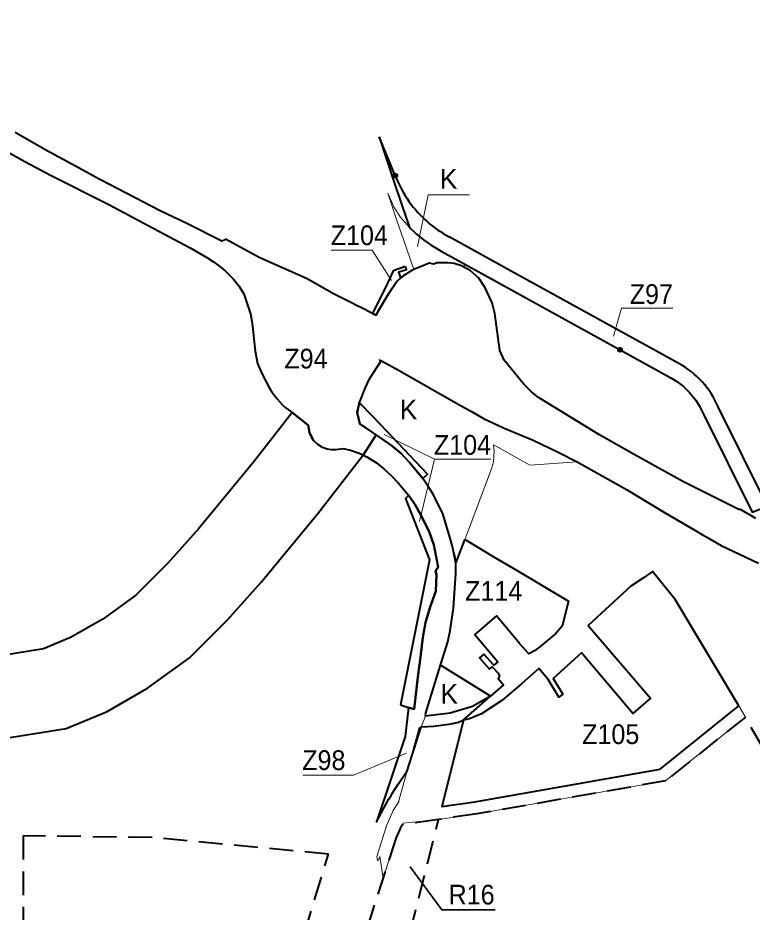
# Model space of a CAD drawing. Extents: x -650276 to -642489, y -1074311 to -1066658.
# Drawn here: x -647038 to -646145, y -1069297 to -1068210 of the extents above; entities that cross this region are included whole.
import ezdxf

# ---------------------------------------------------------------- set-up
doc = ezdxf.new("R2010")
doc.units = 0
doc.header["$LTSCALE"] = 9.6
doc.header["$PDMODE"] = 32
doc.header["$PDSIZE"] = 4.8
doc.linetypes.add('MEDIUM_DASHED', pattern=[4.5, 3, -1.5])
for name, color, linetype, lineweight in [('44', 7, 'Continuous', 40), ('45', 7, 'Continuous', 40), ('46', 7, 'Continuous', 13), ('47', 7, 'Continuous', 13), ('48', 7, 'Continuous', 35), ('61', 7, 'MEDIUM_DASHED', 40), ('62', 7, 'Continuous', 35)]:
    doc.layers.add(name, color=color, linetype=linetype, lineweight=lineweight)

msp = doc.modelspace()

# ---------------------------------------------------------------- linework, layer by layer
at = {"layer": '44'}
msp.add_line((-646578.881, -1068401.54), (-646598.635, -1068354.436), dxfattribs=at)
for points in [[(-647419.713, -1068138.871), (-647405.71, -1068151.74), (-647372.38, -1068179.01), (-647337.74, -1068205.67), (-647334.62, -1068208.02), (-647307.39, -1068227.44), (-647281.64, -1068244.34), (-647234.11, -1068273.04), (-647230.83, -1068274.93), (-647174.56, -1068306.35), (-647142.788, -1068322.462), (-647130.29, -1068328.8), (-647079.16, -1068357.01), (-647032.91, -1068382.51), (-647029.23, -1068384.46), (-646997.06, -1068401.37), (-646929.56, -1068435.42), (-646927.06, -1068436.66)], [(-646545.57, -1068511.42), (-646556.22, -1068515.84), (-646559.72, -1068517.29), (-646569.61, -1068524.1), (-646572.02, -1068526.07), (-646577.07, -1068530.2), (-646587.28, -1068545.28), (-646599.75, -1068566.49), (-646602.21, -1068571.5), (-646606.59, -1068569.33), (-646620.94, -1068561.96), (-646625.86, -1068559.47), (-646631.18, -1068556.77), (-646653.21, -1068545.58), (-646686.84, -1068526.89), (-646686.84, -1068526.89), (-646743.69, -1068501.76), (-646785.05, -1068479.12), (-646787.55, -1068480.36), (-646789.49, -1068481.31), (-646832.29, -1068460.04), (-646864.48, -1068444.64), (-646936.47, -1068407.23), (-646938.95, -1068405.8), (-646967.64, -1068390), (-647002.71, -1068371.09), (-647040.77, -1068349.4)], [(-646598.635, -1068354.436), (-646579.62, -1068411.29), (-646564.78, -1068455.41), (-646561.544, -1068464.842)], [(-646927.06, -1068436.66), (-646854.18, -1068475.8), (-646828.2, -1068489.61), (-646807.82, -1068501.17), (-646799.79, -1068506.39), (-646790.66, -1068513.24), (-646785.34, -1068517.77), (-646779.93, -1068522.9), (-646775.44, -1068527.74), (-646768.95, -1068535.8), (-646763.1, -1068545.18), (-646754.92, -1068569.81), (-646753.35, -1068578.6), (-646752.59, -1068584.55), (-646749.35, -1068615.18), (-646746.32, -1068630.23), (-646740.91, -1068642.34), (-646735.62, -1068652.21), (-646732.25, -1068659.06), (-646729.34, -1068663.94), (-646722.6, -1068673.11), (-646716.39, -1068679.8), (-646716.39, -1068679.8), (-646712.93, -1068683), (-646704.316, -1068689.698), (-646684.7, -1068704.95), (-646682.98, -1068714.07), (-646680.88, -1068719.28), (-646678.08, -1068723.7)], [(-646561.544, -1068464.842), (-646553.677, -1068472.283), (-646544.525, -1068479.79), (-646535.245, -1068486.342), (-646523.105, -1068493.54), (-646493.511, -1068509.855), (-646305.678, -1068613.404)], [(-646234.342, -1068629.893), (-646234.342, -1068629.892), (-646438.626, -1068517.274), (-646513.45, -1068476.025), (-646513.567, -1068475.963)], [(-646337.93, -1068712.4), (-646404.83, -1068671.52), (-646413.45, -1068664.71), (-646422.32, -1068655.58), (-646425.11, -1068652.37), (-646446.54, -1068626.14), (-646451.82, -1068614.31), (-646458.03, -1068569.26), (-646461.14, -1068556.34), (-646469.51, -1068538.15), (-646477.41, -1068526.45), (-646487.92, -1068516.87), (-646498.48, -1068511.26), (-646507.4, -1068508.45), (-646514.39, -1068507.56), (-646528.18, -1068507.58), (-646531.9, -1068509.25), (-646537.71, -1068508.16), (-646545.57, -1068511.42)], [(-646305.678, -1068613.404), (-646243.997, -1068647.407), (-646236.707, -1068651.891), (-646228.691, -1068658.051), (-646221.348, -1068665.144), (-646213.659, -1068674.696), (-646209.179, -1068681.795), (-646204.654, -1068690.937), (-646145.083, -1068810.83), (-646126.317, -1068803.654), (-646186.371, -1068682.825)], [(-646602.095, -1068716.98), (-646622.01, -1068703.3), (-646625.35, -1068689.7), (-646622.68, -1068678.75), (-646615.19, -1068659.11), (-646609.7, -1068647.84), (-646597.4, -1068628.74), (-646596.28, -1068626.52), (-646596.28, -1068626.52), (-646573.14, -1068638.98), (-646545.73, -1068654.81), (-646545.73, -1068654.81), (-646501.64, -1068679.81), (-646486.23, -1068688.54), (-646470.65, -1068697.38), (-646448.02, -1068707.99), (-646444.51, -1068709.64), (-646411.3, -1068723.11), (-646380.94, -1068737.81), (-646357.87, -1068749.64), (-646297.08, -1068783.8), (-646288.37, -1068789.04), (-646251.73, -1068811.04), (-646214.92, -1068832.85), (-646208.7, -1068836.39), (-646205.48, -1068838.23), (-646199.24, -1068841.79), (-646195.52, -1068843.92), (-646182.57, -1068851.3), (-646137.23, -1068872.6)], [(-646704.316, -1068689.698), (-646725.374, -1068716.786), (-646751.116, -1068749.975), (-646817.718, -1068830.545), (-646855.506, -1068872.883), (-646894.206, -1068911.595), (-646934.465, -1068940.759)], [(-646617.991, -1068741.504), (-646622.62, -1068739.32), (-646634.37, -1068735.27), (-646642.04, -1068733.74), (-646651.21, -1068734.99), (-646656.47, -1068735.13), (-646661.5, -1068734.35), (-646667.17, -1068732.38), (-646673.16, -1068728.69), (-646678.08, -1068723.7), (-646680.88, -1068719.28), (-646682.98, -1068714.07), (-646684.7, -1068704.95), (-646704.316, -1068689.698)], [(-646618.655, -1068742.359), (-646617.991, -1068741.504), (-646617.991, -1068741.503), (-646602.095, -1068716.98)], [(-646539.08, -1068779.481), (-646545.32, -1068769.89), (-646561.5, -1068750.22), (-646571.91, -1068739.54), (-646583.49, -1068729.76), (-646602.095, -1068716.98), (-646617.991, -1068741.503)], [(-646140.73, -1068818.61), (-646146.85, -1068814.88), (-646150.26, -1068812.81), (-646159.1, -1068807.43), (-646161.45, -1068807.54), (-646229.44, -1068773.53), (-646288.59, -1068740.88), (-646331.26, -1068716.25), (-646337.93, -1068712.4)], [(-647065.688, -1069087.73), (-646978.92, -1069073.93), (-646929.186, -1069052.925), (-646880.163, -1069024.903), (-646829.104, -1068987.917), (-646782.784, -1068941.581), (-646741.85, -1068895.719), (-646673.05, -1068812.491), (-646618.655, -1068742.359), (-646617.991, -1068741.504)], [(-646617.991, -1068741.503), (-646613.44, -1068743.65), (-646601.86, -1068751.01), (-646592.53, -1068758.66), (-646583.98, -1068766.42), (-646575.28, -1068775.04), (-646562.49, -1068790.69), (-646554.8, -1068801.98)], [(-646509.323, -1068852.529), (-646513.27, -1068838.37), (-646521.18, -1068812.95), (-646532.92, -1068788.95), (-646539.08, -1068779.481)], [(-646554.8, -1068801.98), (-646547.68, -1068814.22), (-646547.433, -1068814.73)], [(-646547.433, -1068814.73), (-646537.35, -1068835.56), (-646532.16, -1068850.47), (-646526.64, -1068877.47), (-646530.06, -1068882.16)], [(-646524, -1068997), (-646514.91, -1068968.48), (-646514.91, -1068968.48), (-646512.07, -1068954.68), (-646507.91, -1068927.47), (-646505.12, -1068885.31), (-646505.17, -1068872.78), (-646509.323, -1068852.529)], [(-646530.06, -1068882.16), (-646528.92, -1068886.55), (-646529.44, -1068906.81), (-646533.28, -1068917.17)], [(-646533.28, -1068917.17), (-646536.54, -1068925.95), (-646542.16, -1068945.12), (-646545.42, -1068963.3), (-646549.17, -1068993.71), (-646549.81, -1068998.88), (-646550.89, -1069007.7), (-646555.84, -1069050.22), (-646559.8, -1069048.98), (-646562.61, -1069048.08)], [(-646934.465, -1068940.759), (-646973.61, -1068963.135), (-647006.63, -1068977.08), (-647076.422, -1068988.18), (-647128.674, -1068991.167), (-647199.672, -1068994.255), (-647268.348, -1068994.255), (-647338.816, -1068991.19), (-647417.895, -1068984.986), (-647502.412, -1068977.157), (-647629.424, -1068964.608), (-647699.561, -1068956.635), (-647749.978, -1068953.416)], [(-646462.98, -1069034.61), (-646485, -1069047), (-646512, -1069055), (-646542, -1069059), (-646541.71, -1069054.76), (-646524, -1068997)], [(-646547.412, -1069071.71), (-646532, -1069071), (-646511, -1069068), (-646502, -1069066), (-646496.317, -1069063.61), (-646462.98, -1069034.61)], [(-646562.61, -1069048.08), (-646566.82, -1069083.62), (-646601.82, -1069187.25), (-646586.97, -1069160.06), (-646585.42, -1069157.56), (-646583.89, -1069155.1), (-646582.46, -1069152.81), (-646582.46, -1069152.81), (-646575.4, -1069141.46), (-646564.54, -1069125.08), (-646547.412, -1069071.71)]]:
    msp.add_lwpolyline(points, dxfattribs=at)
at = {"layer": '44', "lineweight": 13}
for points in [[(-646241.379, -1068562.947), (-646303.746, -1068562.947), (-646313.477, -1068597.03)], [(-646241.379, -1068562.947), (-646303.746, -1068562.947), (-646313.477, -1068597.03)], [(-646691.216, -1069130.395), (-646629.734, -1069130.395), (-646565.156, -1069103.837)], [(-646691.216, -1069130.395), (-646629.734, -1069130.395), (-646565.156, -1069103.837)]]:
    msp.add_lwpolyline(points, dxfattribs=at)
at = {"layer": '44'}
for centre, radius, start, end in [((-646447.332, -1068351.964), 140.58, 200.6496, 215.36619), ((-646447.332, -1068351.964), 140.58, 215.36631, 241.891), ((-646287.447, -1068726.224), 110, 23.23727, 61.13296)]:
    msp.add_arc(centre, radius, start, end, dxfattribs=at)
for p in [(-646578.881, -1068401.54), (-646305.678, -1068613.404)]:
    msp.add_point(p, dxfattribs=at)
at = {"layer": '45'}
msp.add_line((-646583.49, -1068729.76), (-646571.91, -1068739.54), dxfattribs=at)
msp.add_line((-646583.49, -1068729.76), (-646571.91, -1068739.54), dxfattribs=at)
for points in [[(-646566.33, -1068512.04), (-646581.64, -1068517.24), (-646590.31, -1068536.69), (-646602.01, -1068560.15), (-646606.59, -1068569.33)], [(-646566.33, -1068512.04), (-646581.64, -1068517.24), (-646590.31, -1068536.69), (-646602.01, -1068560.15), (-646606.59, -1068569.33)], [(-646587.28, -1068545.28), (-646577.07, -1068530.2), (-646572.02, -1068526.07), (-646574.48, -1068518.75), (-646565.04, -1068515.86), (-646566.33, -1068512.04)], [(-646587.28, -1068545.28), (-646577.07, -1068530.2), (-646572.02, -1068526.07), (-646574.48, -1068518.75), (-646565.04, -1068515.86), (-646566.33, -1068512.04)], [(-646599.75, -1068566.49), (-646587.28, -1068545.28), (-646587.28, -1068545.28)], [(-646599.75, -1068566.49), (-646587.28, -1068545.28), (-646587.28, -1068545.28)], [(-646606.59, -1068569.33), (-646602.21, -1068571.5), (-646599.75, -1068566.49)], [(-646606.59, -1068569.33), (-646602.21, -1068571.5), (-646599.75, -1068566.49)], [(-646571.91, -1068739.54), (-646561.5, -1068750.22), (-646545.32, -1068769.89), (-646539.78, -1068764.65), (-646596.93, -1068704.15), (-646619.74, -1068680.15), (-646622.68, -1068678.75), (-646625.35, -1068689.7)], [(-646571.91, -1068739.54), (-646561.5, -1068750.22), (-646545.32, -1068769.89), (-646539.78, -1068764.65), (-646596.93, -1068704.15), (-646619.74, -1068680.15), (-646622.68, -1068678.75), (-646625.35, -1068689.7)], [(-646625.35, -1068689.7), (-646622.01, -1068703.3), (-646583.49, -1068729.76)], [(-646625.35, -1068689.7), (-646622.01, -1068703.3), (-646583.49, -1068729.76)], [(-646562.49, -1068790.69), (-646566.34, -1068794.32), (-646537.3, -1068868.95), (-646572.42, -1069044.94)], [(-646562.49, -1068790.69), (-646566.34, -1068794.32), (-646537.3, -1068868.95), (-646572.42, -1069044.94)], [(-646526.64, -1068877.47), (-646532.16, -1068850.47), (-646537.35, -1068835.56), (-646547.68, -1068814.22), (-646554.8, -1068801.98), (-646562.49, -1068790.69)], [(-646526.64, -1068877.47), (-646532.16, -1068850.47), (-646537.35, -1068835.56), (-646547.68, -1068814.22), (-646554.8, -1068801.98), (-646562.49, -1068790.69)], [(-646529.44, -1068906.81), (-646528.92, -1068886.55), (-646530.06, -1068882.16), (-646526.64, -1068877.47)], [(-646529.44, -1068906.81), (-646528.92, -1068886.55), (-646530.06, -1068882.16), (-646526.64, -1068877.47)], [(-646555.84, -1069050.22), (-646550.89, -1069007.7), (-646549.81, -1068998.88), (-646549.17, -1068993.71), (-646545.42, -1068963.3), (-646542.16, -1068945.12), (-646536.54, -1068925.95), (-646533.28, -1068917.17), (-646529.44, -1068906.81)], [(-646555.84, -1069050.22), (-646550.89, -1069007.7), (-646549.81, -1068998.88), (-646549.17, -1068993.71), (-646545.42, -1068963.3), (-646542.16, -1068945.12), (-646536.54, -1068925.95), (-646533.28, -1068917.17), (-646529.44, -1068906.81)], [(-646572.42, -1069044.94), (-646562.61, -1069048.08), (-646559.8, -1069048.98), (-646555.84, -1069050.22)], [(-646572.42, -1069044.94), (-646562.61, -1069048.08), (-646559.8, -1069048.98), (-646555.84, -1069050.22)]]:
    msp.add_lwpolyline(points, dxfattribs=at)
for points in [[(-646512.07, -1068954.68), (-646507.91, -1068927.47), (-646505.12, -1068885.31), (-646505.17, -1068872.78), (-646503.24, -1068867.61), (-646494.52, -1068844.29), (-646492.73, -1068845.01), (-646457.86, -1068865.8), (-646430.86, -1068881.89), (-646368.3, -1068919.19), (-646376.02, -1068949.34), (-646383.86, -1068958.24), (-646403.13, -1068974.41), (-646409.67, -1068979.3), (-646416.71, -1068983.21), (-646427.77, -1068970.39), (-646455.78, -1068936.87), (-646458.21, -1068938.99), (-646482.2, -1068959.52), (-646454.21, -1068992.73), (-646459.25, -1068996.98), (-646471.24, -1068983.41), (-646476.35, -1068987.98), (-646464.24, -1069001.49), (-646461.29, -1068998.81), (-646453.48, -1069006.75), (-646452.37, -1069010.01), (-646453.88, -1069013.1), (-646447.2, -1069020.9), (-646462.98, -1069034.61), (-646524, -1068997), (-646514.91, -1068968.48), (-646514.91, -1068968.48)], [(-646512.07, -1068954.68), (-646507.91, -1068927.47), (-646505.12, -1068885.31), (-646505.17, -1068872.78), (-646503.24, -1068867.61), (-646494.52, -1068844.29), (-646492.73, -1068845.01), (-646457.86, -1068865.8), (-646430.86, -1068881.89), (-646368.3, -1068919.19), (-646376.02, -1068949.34), (-646383.86, -1068958.24), (-646403.13, -1068974.41), (-646409.67, -1068979.3), (-646416.71, -1068983.21), (-646427.77, -1068970.39), (-646455.78, -1068936.87), (-646458.21, -1068938.99), (-646482.2, -1068959.52), (-646454.21, -1068992.73), (-646459.25, -1068996.98), (-646471.24, -1068983.41), (-646476.35, -1068987.98), (-646464.24, -1069001.49), (-646461.29, -1068998.81), (-646453.48, -1069006.75), (-646452.37, -1069010.01), (-646453.88, -1069013.1), (-646447.2, -1069020.9), (-646462.98, -1069034.61), (-646524, -1068997), (-646514.91, -1068968.48), (-646514.91, -1068968.48)], [(-646161.484, -1069046.228), (-646238.632, -1068916.799), (-646266.118, -1068883.048), (-646277.268, -1068890.446), (-646292.75, -1068900.72), (-646344.49, -1068948.736), (-646268.528, -1069036.82), (-646290.099, -1069055.423), (-646352.71, -1068981.82), (-646386.936, -1069012.936), (-646375.346, -1069032.07), (-646379.973, -1069035.889), (-646393.09, -1069014.234), (-646404.269, -1069001.033), (-646425.52, -1069019.41), (-646449.418, -1069039.804), (-646474.13, -1069055.83), (-646488.537, -1069062.169), (-646495.89, -1069063.531), (-646522.35, -1069168.648), (-646482.211, -1069162.813), (-646256.824, -1069123.414)], [(-646161.484, -1069046.228), (-646238.632, -1068916.799), (-646266.118, -1068883.048), (-646277.268, -1068890.446), (-646292.75, -1068900.72), (-646344.49, -1068948.736), (-646268.528, -1069036.82), (-646290.099, -1069055.423), (-646352.71, -1068981.82), (-646386.936, -1069012.936), (-646375.346, -1069032.07), (-646379.973, -1069035.889), (-646393.09, -1069014.234), (-646404.269, -1069001.033), (-646425.52, -1069019.41), (-646449.418, -1069039.804), (-646474.13, -1069055.83), (-646488.537, -1069062.169), (-646495.89, -1069063.531), (-646522.35, -1069168.648), (-646482.211, -1069162.813), (-646256.824, -1069123.414)]]:
    msp.add_lwpolyline(points, close=True, dxfattribs=at)
at = {"layer": '46'}
for points in [[(-646656.853, -1068492.089), (-646606.877, -1068492.089), (-646583.419, -1068529.344)], [(-646656.853, -1068492.089), (-646606.877, -1068492.089), (-646583.419, -1068529.344)], [(-646462.83, -1068746.366), (-646531.233, -1068746.366), (-646549.233, -1068822.328), (-646531.233, -1068746.366), (-646592.58, -1068716.54)], [(-646462.83, -1068746.366), (-646531.233, -1068746.366), (-646549.233, -1068822.328), (-646531.233, -1068746.366), (-646592.58, -1068716.54)]]:
    msp.add_lwpolyline(points, dxfattribs=at)
at = {"layer": '47'}
msp.add_line((-646462.98, -1069034.61), (-646524, -1068997), dxfattribs=at)
for points in [[(-646561.544, -1068464.842), (-646572.984, -1068451.81), (-646580.625, -1068439.803), (-646588.07, -1068422.96), (-646576.4, -1068457.27), (-646568.87, -1068479.14), (-646556.22, -1068515.84), (-646545.57, -1068511.42), (-646537.71, -1068508.16)], [(-646523.105, -1068493.54), (-646535.245, -1068486.342), (-646544.525, -1068479.79), (-646553.677, -1068472.283), (-646561.544, -1068464.842)], [(-646537.71, -1068508.16), (-646531.9, -1068509.25), (-646528.18, -1068507.58), (-646514.39, -1068507.56), (-646507.4, -1068508.45), (-646498.48, -1068511.26), (-646495.416, -1068512.888), (-646493.511, -1068509.855), (-646523.105, -1068493.54)], [(-646524, -1068997), (-646541.71, -1069054.76), (-646542, -1069059), (-646547.412, -1069071.71)], [(-646495.89, -1069063.531), (-646496.317, -1069063.61), (-646496.317, -1069063.61), (-646462.98, -1069034.61)], [(-646593.793, -1069255.911), (-646577.878, -1069206.485), (-646572.586, -1069194.485), (-646569.114, -1069188.86), (-646526.31, -1069184.381), (-646479.84, -1069177.626), (-646250.409, -1069137.52), (-646153.307, -1069059.947), (-646161.484, -1069046.228), (-646256.824, -1069123.414)], [(-646256.824, -1069123.414), (-646482.211, -1069162.813), (-646522.35, -1069168.648), (-646495.89, -1069063.531)], [(-646547.412, -1069071.71), (-646549.91, -1069072.542), (-646564.54, -1069125.08), (-646564.605, -1069125.271), (-646574.978, -1069163.017), (-646574.978, -1069163.017), (-646574.33, -1069162.04), (-646575.87, -1069164.54), (-646581.29, -1069173.32), (-646589.56, -1069192.07), (-646601.41, -1069229.34)], [(-646601.41, -1069229.34), (-646600.68, -1069234.21), (-646599.79, -1069234.07), (-646597.77, -1069229.37), (-646596.95, -1069234.83), (-646593.793, -1069255.911)]]:
    msp.add_lwpolyline(points, dxfattribs=at)
msp.add_lwpolyline([(-646513.27, -1068838.37), (-646505.69, -1068865.56), (-646505.17, -1068872.78), (-646503.24, -1068867.61), (-646494.52, -1068844.29), (-646479.45, -1068804.37), (-646461.92, -1068757.93), (-646459.59, -1068750.19), (-646458.57, -1068736.31), (-646459.54, -1068728.94), (-646453.51, -1068732.3), (-646415.3, -1068753.62), (-646357.87, -1068749.64), (-646411.3, -1068723.11), (-646448.02, -1068707.99), (-646470.65, -1068697.38), (-646486.23, -1068688.54), (-646501.64, -1068679.81), (-646545.73, -1068654.81), (-646573.14, -1068638.98), (-646598.59, -1068625.34), (-646597.4, -1068628.74), (-646609.7, -1068647.84), (-646615.19, -1068659.11), (-646622.68, -1068678.75), (-646619.74, -1068680.15), (-646596.93, -1068704.15), (-646539.78, -1068764.65), (-646545.32, -1068769.89), (-646532.92, -1068788.95), (-646521.18, -1068812.95)], close=True, dxfattribs=at)
at = {"layer": '48', "lineweight": 13}
msp.add_lwpolyline([(-646488.64, -1068425), (-646538.869, -1068425), (-646552.014, -1068487.951)], dxfattribs=at)
msp.add_lwpolyline([(-646488.64, -1068425), (-646538.869, -1068425), (-646552.014, -1068487.951)], dxfattribs=at)
at = {"layer": '61'}
for points in [[(-646583.457, -1069759.191), (-646554.262, -1069762.602), (-646321.973, -1069686.855), (-646209.9, -1069538.5), (-646146.8, -1069506.6), (-646148.5, -1069503), (-646028.16, -1069441.58), (-646023.96, -1069440.34), (-646075.49, -1069318.19), (-646025.14, -1069285.394), (-646153.307, -1069059.947)], [(-646153.307, -1069059.947), (-646250.409, -1069137.52), (-646479.84, -1069177.626), (-646526.31, -1069184.381)]]:
    msp.add_lwpolyline(points, dxfattribs=at)
for points in [[(-646572.586, -1069194.485), (-646577.878, -1069206.485), (-646611.107, -1069309.68), (-646626.774, -1069359.349), (-646580.797, -1069364.111), (-646571.479, -1069363.822), (-646526.31, -1069184.381), (-646570.296, -1069190.776)], [(-647031.152, -1069204.288), (-647031.152, -1069353.712), (-647030.324, -1069535.053), (-646842.103, -1069553.182), (-646809.879, -1069353.002), (-646702.425, -1069364.771), (-646659.946, -1069226.375), (-646874.542, -1069206.4)]]:
    msp.add_lwpolyline(points, close=True, dxfattribs=at)
at = {"layer": '62'}
msp.add_lwpolyline([(-646457.55, -1069294.294), (-646522.377, -1069294.294), (-646560.609, -1069241.94)], dxfattribs=at)
at = {"layer": '62', "lineweight": 13}
msp.add_lwpolyline([(-646457.55, -1069294.294), (-646522.377, -1069294.294), (-646560.609, -1069241.94)], dxfattribs=at)

# ---------------------------------------------------------------- texts
at = {"layer": '44', "width": 0.95}
for s, p in [('Z97', (-646293.907, -1068557.715)), ('Z97', (-646293.907, -1068557.715)), ('Z94', (-646713.687, -1068636.144)), ('Z94', (-646713.687, -1068636.144)), ('Z98', (-646691.993, -1069124.279)), ('Z98', (-646691.993, -1069124.279))]:
    msp.add_text(s, height=24, dxfattribs=at).set_placement(p)
at = {"layer": '46', "width": 0.95}
for s, p in [('Z104', (-646657.338, -1068486.184)), ('Z104', (-646657.338, -1068486.184)), ('Z104', (-646531.893, -1068740.983)), ('Z104', (-646531.893, -1068740.983)), ('Z114', (-646493.997, -1068918.587)), ('Z114', (-646493.997, -1068918.587)), ('Z105', (-646351.762, -1069092.692)), ('Z105', (-646351.762, -1069092.692))]:
    msp.add_text(s, height=24, dxfattribs=at).set_placement(p)
at = {"layer": '48'}
for p in [(-646524.8, -1068417.662), (-646524.8, -1068417.662), (-646573.463, -1068697.908), (-646573.463, -1068697.908), (-646524.065, -1069043.743), (-646524.065, -1069043.743)]:
    msp.add_text('K', height=24, dxfattribs=at).set_placement(p)
at = {"layer": '62', "width": 0.95}
msp.add_text('R16', height=24, dxfattribs=at).set_placement((-646514.063, -1069287.733))

doc.saveas('drawing.dxf')
